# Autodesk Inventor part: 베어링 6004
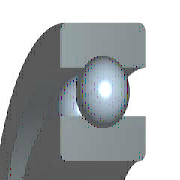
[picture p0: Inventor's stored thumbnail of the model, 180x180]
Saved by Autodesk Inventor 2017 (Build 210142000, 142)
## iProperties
Created: 2012-02
Part Number: 베어링 6004
Material: 강철, 연강
Description: 깊은 그루브 볼 베어링
Document SubType Name: Modeling
Standard: KS B 2023
Designer: mduedu
Standards Organization: KS
Language: ko-KR
Size Designation: 6004 - 20 x 42 x 12
Categories: <MemberInstance><Categories><Category DisplayName="샤프트 부품" InternalName="7f7aeb1f-a693-4053-b835-cee3144e0d98" Mnemonic="SHFT"><Category DisplayName="베어링" Inter
Density: 1 g/cm^3
Appearance: 노란색
IsCustomPart: 1
Author: mduedu
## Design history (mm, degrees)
sketch "스케치" dims "d0" = 5.72 (= -0.26 x WD + 0.26 x BD)
  geometry: L1 (3.14, 15.5)-(8.86, 15.5); L2 (6, 15.5)-(6, 12.64); L3 (6, 15.5)-(6, 18.36); L4 (3.875, 13.586)-(0, 13.586); L5 (0, 10)-(12, 10); L6 (3.875, 17.414)-(0, 17.414); L7 (0, 21)-(12, 21); L8 (12, 10)-(12, 13.586); L9 (8.125, 13.586)-(12, 13.586); L10 (8.125, 17.414)-(12, 17.414); L11 (12, 21)-(12, 17.414); L12 (-1.4, 0)-(8.4, 0) reference; L13 (0, -0.3)-(0, 5.3) reference
  constraints: 22 end point, 4 point on line, 2 collinear, 2 perpendicular, 2 symmetric about line, 1 midpoint, 1 parallel, 14 other
  dimensions: "d9" = 20 diameter of L5 L12 (= WD); "d11" = 42 diameter of L7 L12 (= BD); "d12" = 12 distance between parallel lines of L8 L13 (= KB); "d13" = 27.172 diameter of L9 L12 (= 0.326 x BD + 0.674 x WD)
revolve "본체" stored, may be unused: angle "d6" = 90 deg
revolve "볼" stored, may be unused: angle "d7" = 90 deg
pattern_circular "IDS_ARRAYBALL[SIMPL:T]" dims angle "d3" = 360 deg
body "Solid1"
fillet "모깎기1" dims "d1" = 0.6 (= KRS)
other parameters: "WD" = 20 [user parameter; used in 5 equation terms], "BD" = 42 [user parameter; used in 5 equation terms], "KB" = 12 [user parameter; used in 1 equation term], "KRS" = 0.6 [user parameter; used in 1 equation term], "d4" = 0, "d5" = 0, "d8" = 0, "d14" = 0, "d15" = 0, "BBA" = 0 [user parameter], "BC0" = 5000000 [user parameter], "BC" = 9360000 [user parameter], "BR" = 21 (= 0.5 x BD) [user parameter]
